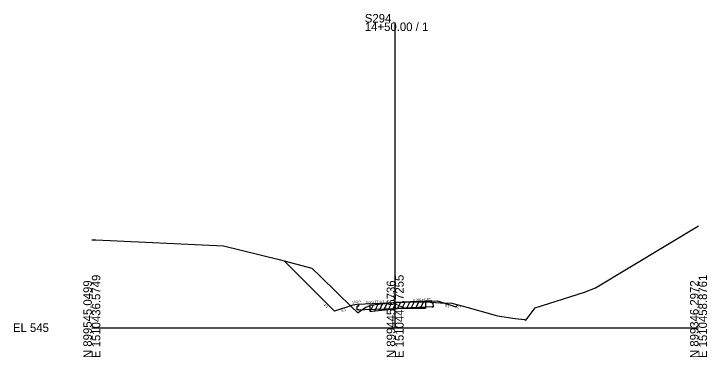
# Model space of a CAD drawing. Extents: x 974 to 2203, y -10 to 19041.
# Drawn here: x 974.3 to 1202.8, y 8990.3 to 9103.4 of the extents above; entities that cross this region are included whole.
import ezdxf

# ---------------------------------------------------------------- set-up
doc = ezdxf.new("R2010")
doc.units = 0
for name, color, linetype in [('RD_GPK_XS_Cell', 7, 'Continuous'), ('RD_XS_Base', 7, 'Continuous'), ('RD_XS_EarthShd', 7, 'Continuous'), ('RD_XS_ExGround', 7, 'Continuous'), ('RD_XS_ExPaveRet', 7, 'Continuous'), ('RD_XS_Pave', 7, 'Continuous'), ('RD_XS_TX_Elev_EX', 7, 'Continuous'), ('RD_XS_TX_Slope', 7, 'Continuous')]:
    doc.layers.add(name, color=color, linetype=linetype)

msp = doc.modelspace()

# ---------------------------------------------------------------- linework, layer by layer
at = {"layer": 'RD_GPK_XS_Cell'}
for p, q in [((1100, 9000), (1100, 9100.6)), ((1000, 9000), (1100, 9000)), ((1100, 9000), (1200, 9000))]:
    msp.add_line(p, q, dxfattribs=at)
at = {"layer": 'RD_XS_Base'}
for p, q in [((1112.05, 9008.15), (1112, 9008.78)), ((1088, 9007.14), (1087.5, 9007.12)), ((1087.5, 9005.85), (1087.5, 9007.12)), ((1088, 9007.14), (1088, 9007.78)), ((1110.16, 9006.8), (1099.99, 9006.37)), ((1112.16, 9006.88), (1110.16, 9006.8)), ((1112.05, 9008.15), (1112.55, 9008.17)), ((1112.16, 9006.88), (1112.66, 9006.9)), ((1112.66, 9006.9), (1112.55, 9008.17)), ((1088, 9005.87), (1087.5, 9005.85)), ((1088, 9005.87), (1090, 9005.96)), ((1090, 9005.96), (1099.99, 9006.37))]:
    msp.add_line(p, q, dxfattribs=at)
at = {"layer": 'RD_XS_EarthShd'}
for p, q in [((1080, 9005.45), (1063.41, 9022.04)), ((1112, 9008.78), (1114, 9008.86)), ((1114, 9008.86), (1120, 9006.86)), ((1086, 9007.45), (1080, 9005.45)), ((1088, 9007.78), (1086, 9007.45)), ((1120, 9006.86), (1120.68, 9007.54))]:
    msp.add_line(p, q, dxfattribs=at)
at = {"layer": 'RD_XS_ExGround'}
msp.add_lwpolyline([(1000, 9028.99), (1001.32, 9028.96), (1043.39, 9027.03), (1061.72, 9022.48), (1072.51, 9019.65), (1075.54, 9016.74), (1085.97, 9006.55), (1087.27, 9005.35), (1087.71, 9004.94), (1088.2, 9005.35), (1090.3, 9006.81), (1091.5, 9007.27), (1091.81, 9007.4), (1093.38, 9007.61), (1100, 9008.27), (1101.44, 9008.42), (1103, 9008.46), (1110.05, 9008.49), (1114.95, 9008.25), (1118.66, 9008.08), (1123.63, 9006.74), (1132.95, 9004.19), (1133.74, 9003.95), (1139.61, 9003.05), (1142.64, 9002.69), (1142.99, 9002.39), (1143.52, 9003.06), (1146.11, 9006.52), (1162.41, 9011.71), (1166, 9013.13), (1200, 9033.53)], dxfattribs=at)
at = {"layer": 'RD_XS_ExPaveRet'}
for p, q in [((1091.81, 9005.4), (1092.88, 9007.54)), ((1091.81, 9005.4), (1091.81, 9007.4)), ((1093.31, 9005.6), (1094.36, 9007.71)), ((1094.81, 9005.75), (1095.86, 9007.86)), ((1096.31, 9005.9), (1097.36, 9008.01)), ((1097.81, 9006.05), (1098.86, 9008.16)), ((1099.31, 9006.2), (1100.36, 9008.31)), ((1100.81, 9006.35), (1101.85, 9008.43)), ((1102.31, 9006.44), (1103.32, 9008.46)), ((1103, 9006.46), (1110.05, 9006.49)), ((1103.81, 9006.46), (1104.81, 9008.47)), ((1105.31, 9006.47), (1106.31, 9008.47)), ((1106.81, 9006.48), (1107.81, 9008.48)), ((1108.31, 9006.48), (1109.31, 9008.48)), ((1110.05, 9008.49), (1110.05, 9006.49)), ((1091.81, 9005.4), (1093.38, 9005.61)), ((1093.38, 9005.61), (1100, 9006.27)), ((1100, 9006.27), (1101.44, 9006.42)), ((1101.44, 9006.42), (1103, 9006.46))]:
    msp.add_line(p, q, dxfattribs=at)
at = {"layer": 'RD_XS_Pave'}
for p, q in [((1112, 9008.78), (1110, 9008.7)), ((1088, 9007.78), (1090, 9007.86)), ((1090, 9007.86), (1100, 9008.28)), ((1110, 9008.7), (1100, 9008.28))]:
    msp.add_line(p, q, dxfattribs=at)

# ---------------------------------------------------------------- texts
at = {"layer": 'RD_GPK_XS_Cell'}
for s, p in [('S294', (1090, 9100.6)), ('14+50.00 / 1', (1090, 9097.8)), ('EL 545', (974, 8998.6))]:
    msp.add_text(s, height=2.8, dxfattribs=at).set_placement(p)
for s, p in [('E 1510436.5749', (1002.8, 8990)), ('E 1510447.7255', (1102.8, 8990)), ('E 1510458.8761', (1202.8, 8990)), ('N 899545.0499', (1000, 8990)), ('N 899445.6736', (1100, 8990)), ('N 899346.2972', (1200, 8990))]:
    msp.add_text(s, height=2.8, rotation=90, dxfattribs=at).set_placement(p)
at = {"layer": 'RD_XS_TX_Elev_EX'}
msp.add_text('549.14', height=0.75, rotation=90, dxfattribs=at).set_placement((1100, 9008.32))
at = {"layer": 'RD_XS_TX_Slope'}
for s, height, rotation, p in [('12.5:1', 0.778, 12.7511, (1085.88, 9007.91)), ('0.020 FT./FT.', 0.7518, 1.8449, (1090.38, 9008.04)), ('0.020 FT./FT.', 0.7518, 2.1396, (1105.93, 9008.74)), ('2:1', 0.778, 319.3411, (1076.37, 9007.4)), ('6:1', 0.778, 340.6018, (1116.36, 9007.07)), ('2:1', 0.778, 40.6589, (1120.67, 9005.99)), ('6:1', 0.778, 19.3982, (1082.46, 9005.14))]:
    msp.add_text(s, height=height, rotation=rotation, dxfattribs=at).set_placement(p)

doc.saveas('drawing.dxf')
